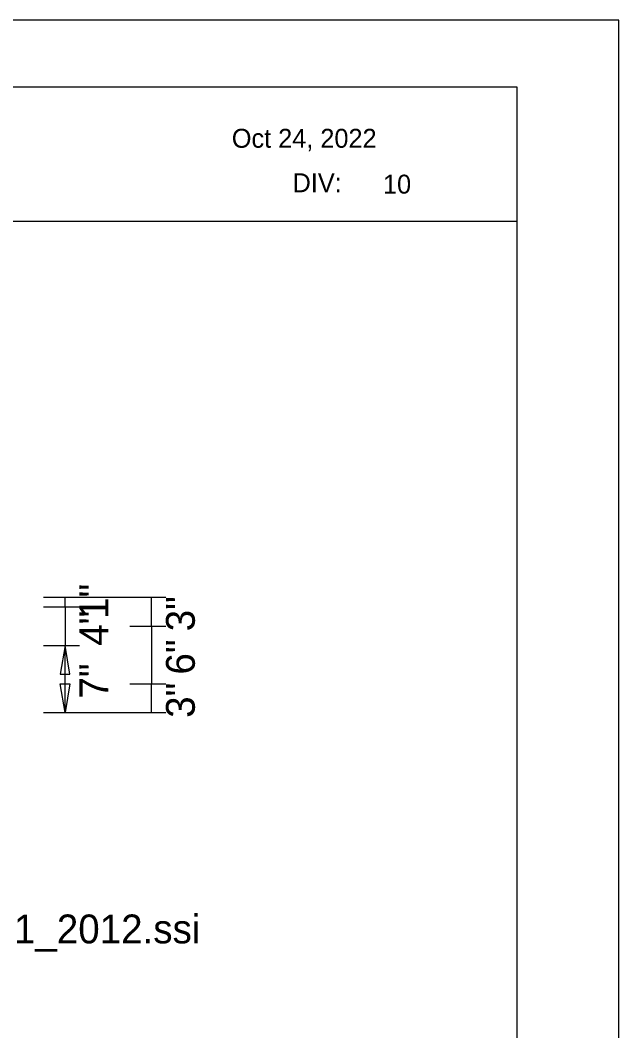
# Model space of a CAD drawing. Extents: x 1708.4 to 1771.6, y 238.3 to 283.4.
# Drawn here: x 1732.21 to 1738.44, y 248.77 to 259.28 of the extents above; entities that cross this region are included whole.
import ezdxf

# ---------------------------------------------------------------- set-up
doc = ezdxf.new("R2010")
doc.units = 0
for name, color, linetype in [('Level 5', 7, 'Continuous'), ('Level 6', 7, 'Continuous'), ('Level 7', 7, 'Continuous'), ('Level 9', 7, 'Continuous')]:
    doc.layers.add(name, color=color, linetype=linetype)

msp = doc.modelspace()

# ---------------------------------------------------------------- linework, layer by layer
at = {"layer": 'Level 5'}
for p, q in [((1732.45, 253.275), (1732.825, 253.275)), ((1732.45, 253.275), (1733.35, 253.275)), ((1732.675, 253.175), (1732.675, 253.275)), ((1733.35, 253.275), (1733.725, 253.275)), ((1733.575, 252.975), (1733.575, 253.275)), ((1732.45, 253.175), (1732.825, 253.175)), ((1732.45, 253.175), (1732.825, 253.175)), ((1732.675, 253.175), (1732.675, 252.775)), ((1733.35, 252.975), (1733.725, 252.975)), ((1733.35, 252.975), (1733.725, 252.975)), ((1733.575, 252.975), (1733.575, 252.375)), ((1732.45, 252.775), (1732.825, 252.775)), ((1732.45, 252.775), (1732.825, 252.775)), ((1732.675, 252.075), (1732.675, 252.775)), ((1733.35, 252.375), (1733.725, 252.375)), ((1733.35, 252.375), (1733.725, 252.375)), ((1733.575, 252.075), (1733.575, 252.375)), ((1732.45, 252.075), (1732.825, 252.075)), ((1732.45, 252.075), (1733.35, 252.075)), ((1733.35, 252.075), (1733.725, 252.075))]:
    msp.add_line(p, q, dxfattribs=at)
for points in [[(1732.675, 252.775), (1732.625, 252.475), (1732.725, 252.475)], [(1732.675, 252.075), (1732.625, 252.375), (1732.725, 252.375)]]:
    msp.add_lwpolyline(points, close=True, dxfattribs=at)
at = {"layer": 'Level 6'}
msp.add_line((1720.221, 257.186), (1737.376, 257.186), dxfattribs=at)
msp.add_lwpolyline([(1709.065, 258.583), (1737.376, 258.583), (1737.376, 238.927), (1709.065, 238.927)], close=True, dxfattribs=at)
at = {"layer": 'Level 9'}
msp.add_lwpolyline([(1708.374, 238.254), (1738.436, 238.254), (1738.436, 259.278), (1708.374, 259.278)], close=True, dxfattribs=at)

# ---------------------------------------------------------------- texts
at = {"layer": 'Level 5'}
for s, p in [('1"', (1733.125, 253.05)), ('3"', (1734.025, 252.921)), ('4"', (1733.125, 252.771)), ('6"', (1734.025, 252.471)), ('7"', (1733.125, 252.221)), ('3"', (1734.025, 252.021))]:
    msp.add_text(s, height=0.3, rotation=90, dxfattribs=at).set_placement(p)
msp.add_text('Panel Style: guide_con_street name_c1_2012.ssi', height=0.3, dxfattribs=at).set_placement((1725.274, 249.675))
at = {"layer": 'Level 6'}
msp.add_text('DIV:', height=0.1968, rotation=360, dxfattribs=at).set_placement((1735.042, 257.488))
msp.add_text('10', height=0.1968, dxfattribs=at).set_placement((1735.983, 257.474))
at = {"layer": 'Level 7'}
msp.add_text('Oct 24, 2022', height=0.19675, dxfattribs=at).set_placement((1734.41, 257.951))

doc.saveas('drawing.dxf')
